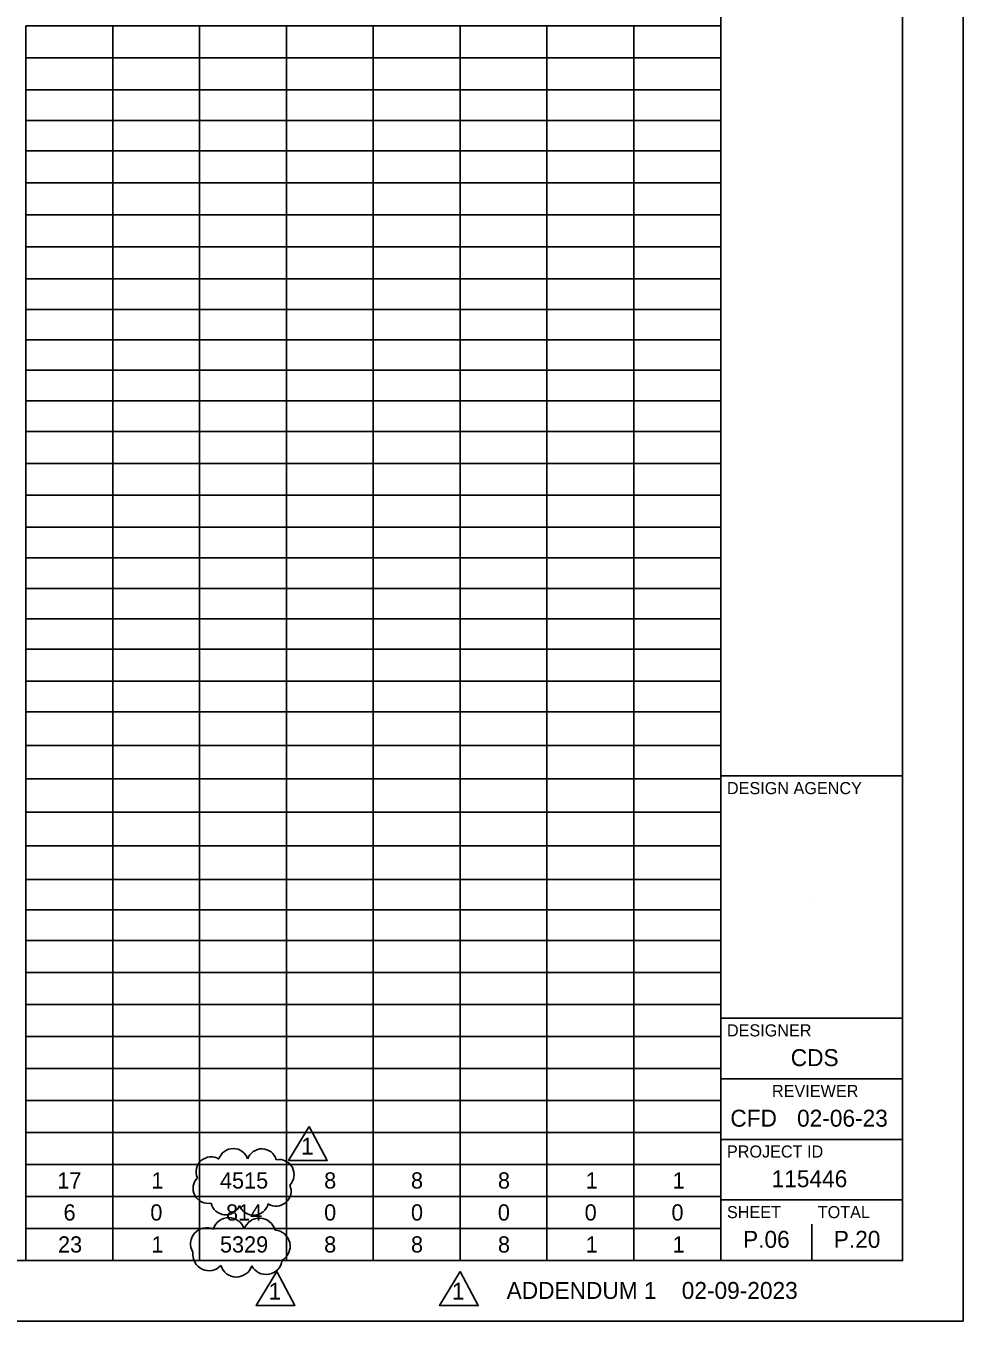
# Model space of a CAD drawing. Extents: x 0 to 34, y 0 to 22.
# Drawn here: x 26.26 to 34, y 0 to 10.69 of the extents above; entities that cross this region are included whole.
import ezdxf

# ---------------------------------------------------------------- set-up
doc = ezdxf.new("R2010")
doc.units = 0
for name, color, linetype in [('Default', 7, 'Continuous'), ('SH_Border', 7, 'Continuous'), ('SH_Cut_Line', 7, 'Continuous'), ('SH_Data', 7, 'Continuous'), ('SH_Text', 7, 'Continuous')]:
    doc.layers.add(name, color=color, linetype=linetype)

msp = doc.modelspace()

# ---------------------------------------------------------------- linework, layer by layer
at = {"layer": 'Default'}
for points in [[(28.601, 1.606), (28.43, 1.327), (28.75, 1.326)], [(28.333, 0.409), (28.162, 0.13), (28.482, 0.128)], [(29.846, 0.409), (29.676, 0.13), (29.996, 0.128)]]:
    msp.add_lwpolyline(points, close=True, dxfattribs=at)
for centre, radius, start, end in [((27.974, 1.301), 0.124, 17.5, 162.5), ((28.21, 1.298), 0.124, 16.0094, 161.0094), ((27.791, 1.232), 0.124, 58.587, 203.587), ((28.352, 1.21), 0.124, 315.4399, 100.4399), ((27.766, 1.096), 0.124, 135.7907, 280.7907), ((28.327, 1.073), 0.124, 238.6516, 23.6516), ((27.911, 1.001), 0.124, 192.6655, 337.6655), ((28.142, 0.998), 0.124, 200.6547, 345.6547), ((27.755, 0.637), 0.134, 66.0655, 211.0655), ((27.937, 0.72), 0.134, 18.0444, 163.0444), ((28.19, 0.716), 0.134, 15.1851, 160.1851), ((28.309, 0.618), 0.134, 300.6438, 85.6438), ((27.773, 0.55), 0.134, 172.2714, 317.2714), ((27.999, 0.498), 0.134, 196.8729, 341.8729), ((28.244, 0.519), 0.134, 208.0439, 353.0439)]:
    msp.add_arc(centre, radius, start, end, dxfattribs=at)
at = {"layer": 'SH_Border'}
for p, q in [((32, 0.5), (32, 21.5)), ((32, 4.5), (33.5, 4.5)), ((32, 2.5), (33.5, 2.5)), ((32, 2), (33.5, 2)), ((32, 1.5), (33.5, 1.5)), ((32, 1), (33.5, 1))]:
    msp.add_line(p, q, dxfattribs=at)
msp.add_lwpolyline([(1.5, 21.5), (33.5, 21.5), (33.5, 0.5), (1.5, 0.5)], close=True, dxfattribs=at)
at = {"layer": 'SH_Cut_Line'}
msp.add_lwpolyline([(0, 0), (34, 0), (34, 22), (0, 22)], close=True, dxfattribs=at)
at = {"layer": 'SH_Data'}
for p, q in [((32.75, 3.5), (32.75, 3.5)), ((32.75, 0.5), (32.75, 0.8)), ((32.375, 0.675), (32.375, 0.675))]:
    msp.add_line(p, q, dxfattribs=at)
at = {"layer": 'SH_Text'}
for p, q in [((26.261, 10.692), (28.413, 10.692)), ((26.261, 10.692), (26.261, 10.428)), ((26.979, 10.692), (26.979, 10.428)), ((27.696, 10.692), (27.696, 10.428)), ((28.413, 10.692), (29.13, 10.692)), ((28.413, 10.692), (28.413, 10.428)), ((29.13, 10.692), (29.847, 10.692)), ((29.13, 10.692), (29.13, 10.428)), ((29.847, 10.692), (31.999, 10.692)), ((29.847, 10.692), (29.847, 10.428)), ((30.564, 10.692), (30.564, 10.428)), ((31.282, 10.692), (31.282, 10.428)), ((31.999, 10.692), (31.999, 10.428)), ((26.261, 10.428), (28.413, 10.428)), ((26.261, 10.428), (26.261, 10.164)), ((26.979, 10.428), (26.979, 10.164)), ((27.696, 10.428), (27.696, 10.164)), ((28.413, 10.428), (29.13, 10.428)), ((28.413, 10.428), (28.413, 10.164)), ((29.13, 10.428), (29.847, 10.428)), ((29.13, 10.428), (29.13, 10.164)), ((29.847, 10.428), (31.999, 10.428)), ((29.847, 10.428), (29.847, 10.164)), ((30.564, 10.428), (30.564, 10.164)), ((31.282, 10.428), (31.282, 10.164)), ((31.999, 10.428), (31.999, 10.164)), ((26.261, 10.164), (28.413, 10.164)), ((26.261, 10.164), (26.261, 9.396)), ((26.979, 10.164), (26.979, 9.396)), ((27.696, 10.164), (27.696, 9.396)), ((28.413, 10.164), (29.13, 10.164)), ((28.413, 10.164), (28.413, 9.396)), ((29.13, 10.164), (29.847, 10.164)), ((29.13, 10.164), (29.13, 9.396)), ((29.847, 10.164), (31.999, 10.164)), ((29.847, 10.164), (29.847, 9.396)), ((30.564, 10.164), (30.564, 9.396)), ((31.282, 10.164), (31.282, 9.396)), ((31.999, 10.164), (31.999, 9.396)), ((26.261, 9.912), (28.413, 9.912)), ((28.413, 9.912), (29.13, 9.912)), ((29.13, 9.912), (29.847, 9.912)), ((29.847, 9.912), (31.999, 9.912)), ((26.261, 9.66), (28.413, 9.66)), ((28.413, 9.66), (29.13, 9.66)), ((29.13, 9.66), (29.847, 9.66)), ((29.847, 9.66), (31.999, 9.66)), ((26.261, 9.396), (28.413, 9.396)), ((26.261, 9.396), (26.261, 9.132)), ((26.979, 9.396), (26.979, 9.132)), ((27.696, 9.396), (27.696, 9.132)), ((28.413, 9.396), (29.13, 9.396)), ((28.413, 9.396), (28.413, 9.132)), ((29.13, 9.396), (29.847, 9.396)), ((29.13, 9.396), (29.13, 9.132)), ((29.847, 9.396), (31.999, 9.396)), ((29.847, 9.396), (29.847, 9.132)), ((30.564, 9.396), (30.564, 9.132)), ((31.282, 9.396), (31.282, 9.132)), ((31.999, 9.396), (31.999, 9.132)), ((26.261, 9.132), (28.413, 9.132)), ((26.261, 9.132), (26.261, 8.868)), ((26.979, 9.132), (26.979, 8.868)), ((27.696, 9.132), (27.696, 8.868)), ((28.413, 9.132), (29.13, 9.132)), ((28.413, 9.132), (28.413, 8.868)), ((29.13, 9.132), (29.847, 9.132)), ((29.13, 9.132), (29.13, 8.868)), ((29.847, 9.132), (31.999, 9.132)), ((29.847, 9.132), (29.847, 8.868)), ((30.564, 9.132), (30.564, 8.868)), ((31.282, 9.132), (31.282, 8.868)), ((31.999, 9.132), (31.999, 8.868)), ((26.261, 8.868), (28.413, 8.868)), ((26.261, 8.868), (26.261, 8.604)), ((26.979, 8.868), (26.979, 8.604)), ((27.696, 8.868), (27.696, 8.604)), ((28.413, 8.868), (29.13, 8.868)), ((28.413, 8.868), (28.413, 8.604)), ((29.13, 8.868), (29.847, 8.868)), ((29.13, 8.868), (29.13, 8.604)), ((29.847, 8.868), (31.999, 8.868)), ((29.847, 8.868), (29.847, 8.604)), ((30.564, 8.868), (30.564, 8.604)), ((31.282, 8.868), (31.282, 8.604)), ((31.999, 8.868), (31.999, 8.604)), ((26.261, 8.604), (28.413, 8.604)), ((26.261, 8.604), (26.261, 7.081)), ((26.979, 8.604), (26.979, 7.081)), ((27.696, 8.604), (27.696, 7.081)), ((28.413, 8.604), (29.13, 8.604)), ((28.413, 8.604), (28.413, 7.081)), ((29.13, 8.604), (29.847, 8.604)), ((29.13, 8.604), (29.13, 7.081)), ((29.847, 8.604), (31.999, 8.604)), ((29.847, 8.604), (29.847, 7.081)), ((30.564, 8.604), (30.564, 7.081)), ((31.282, 8.604), (31.282, 7.081)), ((31.999, 8.604), (31.999, 7.081)), ((26.261, 8.352), (28.413, 8.352)), ((28.413, 8.352), (29.13, 8.352)), ((29.13, 8.352), (29.847, 8.352)), ((29.847, 8.352), (31.999, 8.352)), ((26.261, 8.1), (28.413, 8.1)), ((28.413, 8.1), (29.13, 8.1)), ((29.13, 8.1), (29.847, 8.1)), ((29.847, 8.1), (31.999, 8.1)), ((26.261, 7.849), (28.413, 7.849)), ((28.413, 7.849), (29.13, 7.849)), ((29.13, 7.849), (29.847, 7.849)), ((29.847, 7.849), (31.999, 7.849)), ((26.261, 7.597), (28.413, 7.597)), ((28.413, 7.597), (29.13, 7.597)), ((29.13, 7.597), (29.847, 7.597)), ((29.847, 7.597), (31.999, 7.597)), ((26.261, 7.345), (28.413, 7.345)), ((28.413, 7.345), (29.13, 7.345)), ((29.13, 7.345), (29.847, 7.345)), ((29.847, 7.345), (31.999, 7.345)), ((26.261, 7.081), (28.413, 7.081)), ((26.261, 7.081), (26.261, 6.817)), ((26.979, 7.081), (26.979, 6.817)), ((27.696, 7.081), (27.696, 6.817)), ((28.413, 7.081), (29.13, 7.081)), ((28.413, 7.081), (28.413, 6.817)), ((29.13, 7.081), (29.847, 7.081)), ((29.13, 7.081), (29.13, 6.817)), ((29.847, 7.081), (31.999, 7.081)), ((29.847, 7.081), (29.847, 6.817)), ((30.564, 7.081), (30.564, 6.817)), ((31.282, 7.081), (31.282, 6.817)), ((31.999, 7.081), (31.999, 6.817)), ((26.261, 6.817), (28.413, 6.817)), ((26.261, 6.817), (26.261, 5.282)), ((26.979, 6.817), (26.979, 5.282)), ((27.696, 6.817), (27.696, 5.282)), ((28.413, 6.817), (29.13, 6.817)), ((28.413, 6.817), (28.413, 5.282)), ((29.13, 6.817), (29.847, 6.817)), ((29.13, 6.817), (29.13, 5.282)), ((29.847, 6.817), (31.999, 6.817)), ((29.847, 6.817), (29.847, 5.282)), ((30.564, 6.817), (30.564, 5.282)), ((31.282, 6.817), (31.282, 5.282)), ((31.999, 6.817), (31.999, 5.282)), ((26.261, 6.553), (28.413, 6.553)), ((28.413, 6.553), (29.13, 6.553)), ((29.13, 6.553), (29.847, 6.553)), ((29.847, 6.553), (31.999, 6.553)), ((26.261, 6.301), (28.413, 6.301)), ((28.413, 6.301), (29.13, 6.301)), ((29.13, 6.301), (29.847, 6.301)), ((29.847, 6.301), (31.999, 6.301)), ((26.261, 6.049), (28.413, 6.049)), ((28.413, 6.049), (29.13, 6.049)), ((29.13, 6.049), (29.847, 6.049)), ((29.847, 6.049), (31.999, 6.049)), ((26.261, 5.798), (28.413, 5.798)), ((28.413, 5.798), (29.13, 5.798)), ((29.13, 5.798), (29.847, 5.798)), ((29.847, 5.798), (31.999, 5.798)), ((26.261, 5.546), (28.413, 5.546)), ((28.413, 5.546), (29.13, 5.546)), ((29.13, 5.546), (29.847, 5.546)), ((29.847, 5.546), (31.999, 5.546)), ((26.261, 5.282), (28.413, 5.282)), ((26.261, 5.282), (26.261, 4.477)), ((26.979, 5.282), (26.979, 4.477)), ((27.696, 5.282), (27.696, 4.477)), ((28.413, 5.282), (29.13, 5.282)), ((28.413, 5.282), (28.413, 4.477)), ((29.13, 5.282), (29.847, 5.282)), ((29.13, 5.282), (29.13, 4.477)), ((29.847, 5.282), (31.999, 5.282)), ((29.847, 5.282), (29.847, 4.477)), ((30.564, 5.282), (30.564, 4.477)), ((31.282, 5.282), (31.282, 4.477)), ((31.999, 5.282), (31.999, 4.477)), ((26.261, 5.03), (28.413, 5.03)), ((28.413, 5.03), (29.13, 5.03)), ((29.13, 5.03), (29.847, 5.03)), ((29.847, 5.03), (31.999, 5.03)), ((26.261, 4.753), (28.413, 4.753)), ((28.413, 4.753), (29.13, 4.753)), ((29.13, 4.753), (29.847, 4.753)), ((29.847, 4.753), (31.999, 4.753)), ((26.261, 4.477), (28.413, 4.477)), ((26.261, 4.477), (26.261, 3.646)), ((26.979, 4.477), (26.979, 3.646)), ((27.696, 4.477), (27.696, 3.646)), ((28.413, 4.477), (29.13, 4.477)), ((28.413, 4.477), (28.413, 3.646)), ((29.13, 4.477), (29.847, 4.477)), ((29.13, 4.477), (29.13, 3.646)), ((29.847, 4.477), (31.999, 4.477)), ((29.847, 4.477), (29.847, 3.646)), ((30.564, 4.477), (30.564, 3.646)), ((31.282, 4.477), (31.282, 3.646)), ((31.999, 4.477), (31.999, 3.646)), ((26.261, 4.2), (28.413, 4.2)), ((28.413, 4.2), (29.13, 4.2)), ((29.13, 4.2), (29.847, 4.2)), ((29.847, 4.2), (31.999, 4.2)), ((26.261, 3.923), (28.413, 3.923)), ((28.413, 3.923), (29.13, 3.923)), ((29.13, 3.923), (29.847, 3.923)), ((29.847, 3.923), (31.999, 3.923)), ((26.261, 3.646), (28.413, 3.646)), ((26.261, 3.646), (26.261, 2.35)), ((26.979, 3.646), (26.979, 2.35)), ((27.696, 3.646), (27.696, 2.35)), ((28.413, 3.646), (29.13, 3.646)), ((28.413, 3.646), (28.413, 2.35)), ((29.13, 3.646), (29.847, 3.646)), ((29.13, 3.646), (29.13, 2.35)), ((29.847, 3.646), (31.999, 3.646)), ((29.847, 3.646), (29.847, 2.35)), ((30.564, 3.646), (30.564, 2.35)), ((31.282, 3.646), (31.282, 2.35)), ((31.999, 3.646), (31.999, 2.35)), ((26.261, 3.395), (28.413, 3.395)), ((28.413, 3.395), (29.13, 3.395)), ((29.13, 3.395), (29.847, 3.395)), ((29.847, 3.395), (31.999, 3.395)), ((26.261, 3.143), (28.413, 3.143)), ((28.413, 3.143), (29.13, 3.143)), ((29.13, 3.143), (29.847, 3.143)), ((29.847, 3.143), (31.999, 3.143)), ((26.261, 2.879), (28.413, 2.879)), ((28.413, 2.879), (29.13, 2.879)), ((29.13, 2.879), (29.847, 2.879)), ((29.847, 2.879), (31.999, 2.879)), ((26.261, 2.614), (28.413, 2.614)), ((28.413, 2.614), (29.13, 2.614)), ((29.13, 2.614), (29.847, 2.614)), ((29.847, 2.614), (31.999, 2.614)), ((26.261, 2.35), (28.413, 2.35)), ((26.261, 2.35), (26.261, 1.822)), ((26.979, 2.35), (26.979, 1.822)), ((27.696, 2.35), (27.696, 1.822)), ((28.413, 2.35), (29.13, 2.35)), ((28.413, 2.35), (28.413, 1.822)), ((29.13, 2.35), (29.847, 2.35)), ((29.13, 2.35), (29.13, 1.822)), ((29.847, 2.35), (31.999, 2.35)), ((29.847, 2.35), (29.847, 1.822)), ((30.564, 2.35), (30.564, 1.822)), ((31.282, 2.35), (31.282, 1.822)), ((31.999, 2.35), (31.999, 1.822)), ((26.261, 2.086), (28.413, 2.086)), ((28.413, 2.086), (29.13, 2.086)), ((29.13, 2.086), (29.847, 2.086)), ((29.847, 2.086), (31.999, 2.086)), ((26.261, 1.822), (28.413, 1.822)), ((26.261, 1.822), (26.261, 1.558)), ((26.979, 1.822), (26.979, 1.558)), ((27.696, 1.822), (27.696, 1.558)), ((28.413, 1.822), (29.13, 1.822)), ((28.413, 1.822), (28.413, 1.558)), ((29.13, 1.822), (29.847, 1.822)), ((29.13, 1.822), (29.13, 1.558)), ((29.847, 1.822), (31.999, 1.822)), ((29.847, 1.822), (29.847, 1.558)), ((30.564, 1.822), (30.564, 1.558)), ((31.282, 1.822), (31.282, 1.558)), ((31.999, 1.822), (31.999, 1.558)), ((26.261, 1.558), (28.413, 1.558)), ((26.261, 1.558), (26.261, 1.029)), ((26.979, 1.558), (26.979, 1.029)), ((27.696, 1.558), (27.696, 1.029)), ((28.413, 1.558), (29.13, 1.558)), ((28.413, 1.558), (28.413, 1.029)), ((29.13, 1.558), (29.847, 1.558)), ((29.13, 1.558), (29.13, 1.029)), ((29.847, 1.558), (31.999, 1.558)), ((29.847, 1.558), (29.847, 1.029)), ((30.564, 1.558), (30.564, 1.029)), ((31.282, 1.558), (31.282, 1.029)), ((31.999, 1.558), (31.999, 1.029)), ((26.261, 1.293), (28.413, 1.293)), ((28.413, 1.293), (29.13, 1.293)), ((29.13, 1.293), (29.847, 1.293)), ((29.847, 1.293), (31.999, 1.293)), ((26.261, 1.029), (28.413, 1.029)), ((26.261, 1.029), (26.261, 0.501)), ((26.979, 1.029), (26.979, 0.501)), ((27.696, 1.029), (27.696, 0.501)), ((28.413, 1.029), (29.13, 1.029)), ((28.413, 1.029), (28.413, 0.501)), ((29.13, 1.029), (29.847, 1.029)), ((29.13, 1.029), (29.13, 0.501)), ((29.847, 1.029), (31.999, 1.029)), ((29.847, 1.029), (29.847, 0.501)), ((30.564, 1.029), (30.564, 0.501)), ((31.282, 1.029), (31.282, 0.501)), ((31.999, 1.029), (31.999, 0.501)), ((26.261, 0.765), (28.413, 0.765)), ((28.413, 0.765), (29.13, 0.765)), ((29.13, 0.765), (29.847, 0.765)), ((29.847, 0.765), (31.999, 0.765)), ((26.261, 0.501), (28.413, 0.501)), ((28.413, 0.501), (29.13, 0.501)), ((29.13, 0.501), (29.847, 0.501)), ((29.847, 0.501), (31.999, 0.501))]:
    msp.add_line(p, q, dxfattribs=at)

# ---------------------------------------------------------------- texts
at = {"layer": 'Default'}
for s, p in [('1', (28.533, 1.374)), ('ADDENDUM 1    02-09-2023', (30.231, 0.183)), ('1', (28.265, 0.177)), ('1', (29.779, 0.177))]:
    msp.add_text(s, height=0.14, dxfattribs=at).set_placement(p)
at = {"layer": 'SH_Data'}
for s, height, p in [('DESIGN AGENCY', 0.1, (32.05, 4.35)), ('DESIGNER', 0.1, (32.05, 2.35)), ('CDS', 0.14, (32.577, 2.105)), ('REVIEWER', 0.1, (32.422, 1.85)), ('CFD', 0.14, (32.078, 1.605)), ('02-06-23', 0.14, (32.629, 1.605)), ('PROJECT ID', 0.1, (32.05, 1.35)), ('115446', 0.14, (32.419, 1.105)), ('SHEET', 0.1, (32.05, 0.85)), ('TOTAL', 0.1, (32.8, 0.85)), ('P.06', 0.14, (32.183, 0.605)), ('P.20', 0.14, (32.932, 0.605))]:
    msp.add_text(s, height=height, dxfattribs=at).set_placement(p)
at = {"layer": 'SH_Text'}
for s, height, p in [('17', 0.1337, (26.521, 1.094)), ('1', 0.134, (27.298, 1.094)), ('4515', 0.1337, (27.864, 1.094)), ('8', 0.134, (28.724, 1.094)), ('8', 0.134, (29.441, 1.094)), ('8', 0.134, (30.159, 1.094)), ('1', 0.134, (30.884, 1.094)), ('1', 0.134, (31.601, 1.094)), ('6', 0.134, (26.572, 0.83)), ('0', 0.134, (27.289, 0.83)), ('814', 0.1337, (27.914, 0.83)), ('0', 0.134, (28.724, 0.83)), ('0', 0.134, (29.441, 0.83)), ('0', 0.134, (30.158, 0.83)), ('0', 0.134, (30.875, 0.83)), ('0', 0.134, (31.592, 0.83)), ('23', 0.1337, (26.527, 0.566)), ('1', 0.134, (27.298, 0.566)), ('5329', 0.1337, (27.864, 0.566)), ('8', 0.134, (28.724, 0.566)), ('8', 0.134, (29.441, 0.566)), ('8', 0.134, (30.159, 0.566)), ('1', 0.134, (30.884, 0.566)), ('1', 0.134, (31.601, 0.566))]:
    msp.add_text(s, height=height, dxfattribs=at).set_placement(p)

doc.saveas('drawing.dxf')
